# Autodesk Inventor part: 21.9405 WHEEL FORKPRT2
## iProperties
Created: 2010-10
Part Number: 21.9405 WHEEL FORKPRT2
Document SubType Name: Modeling
Designer: Administrator
Density: 7.85 g/cm^3
Material: Steel
Mass: 199.931 g
Surface Area: 127.303 cm^2
Volume: 25.4689 cm^3
Author: Administrator
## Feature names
1. Base1
